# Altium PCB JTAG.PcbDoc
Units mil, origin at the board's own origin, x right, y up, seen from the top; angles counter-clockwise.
Board outline 6010.03 x 2260.03 mil, 2 copper layers (Top, Bottom), stack 62 mil thick; 63 components, 99 nets, 391 pads, 117 vias.
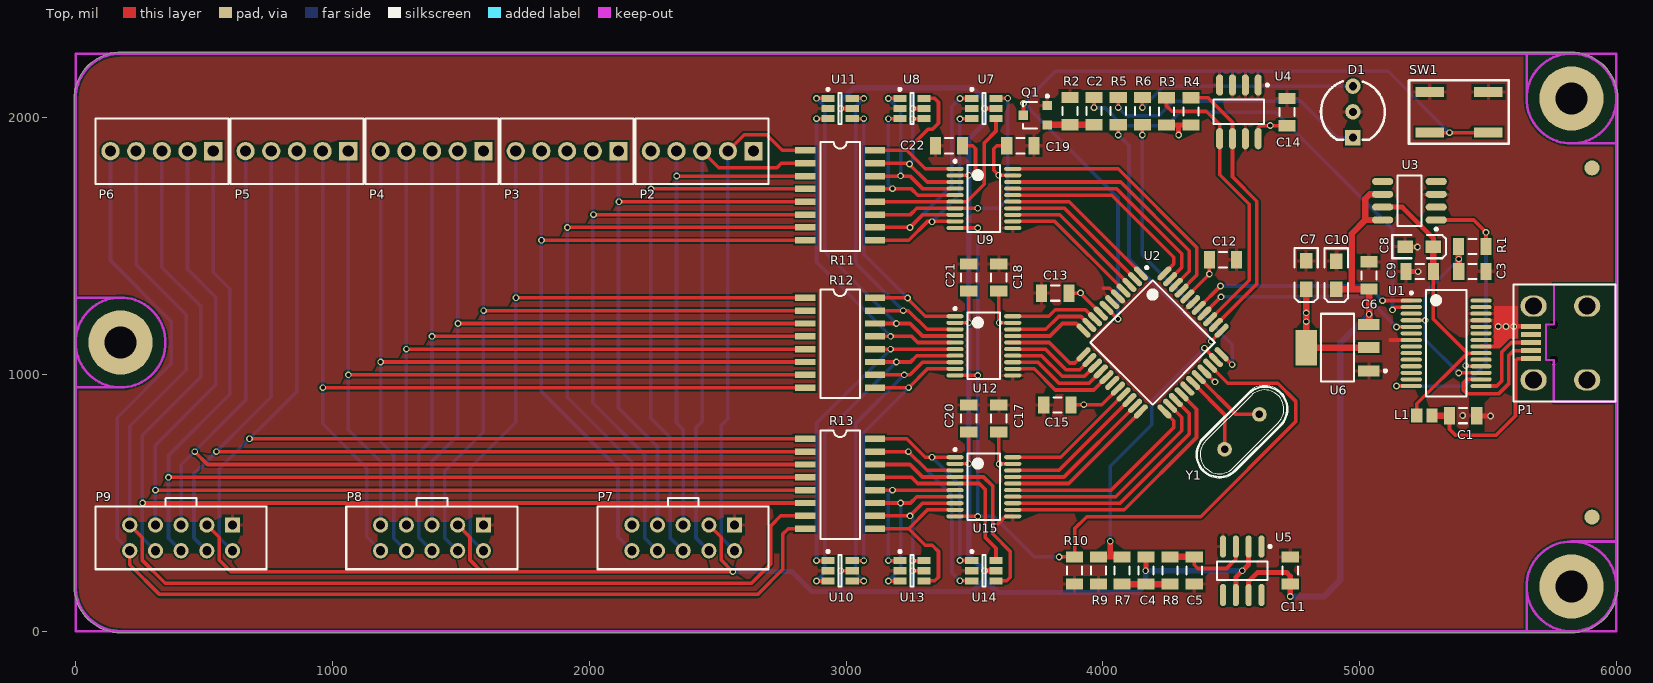
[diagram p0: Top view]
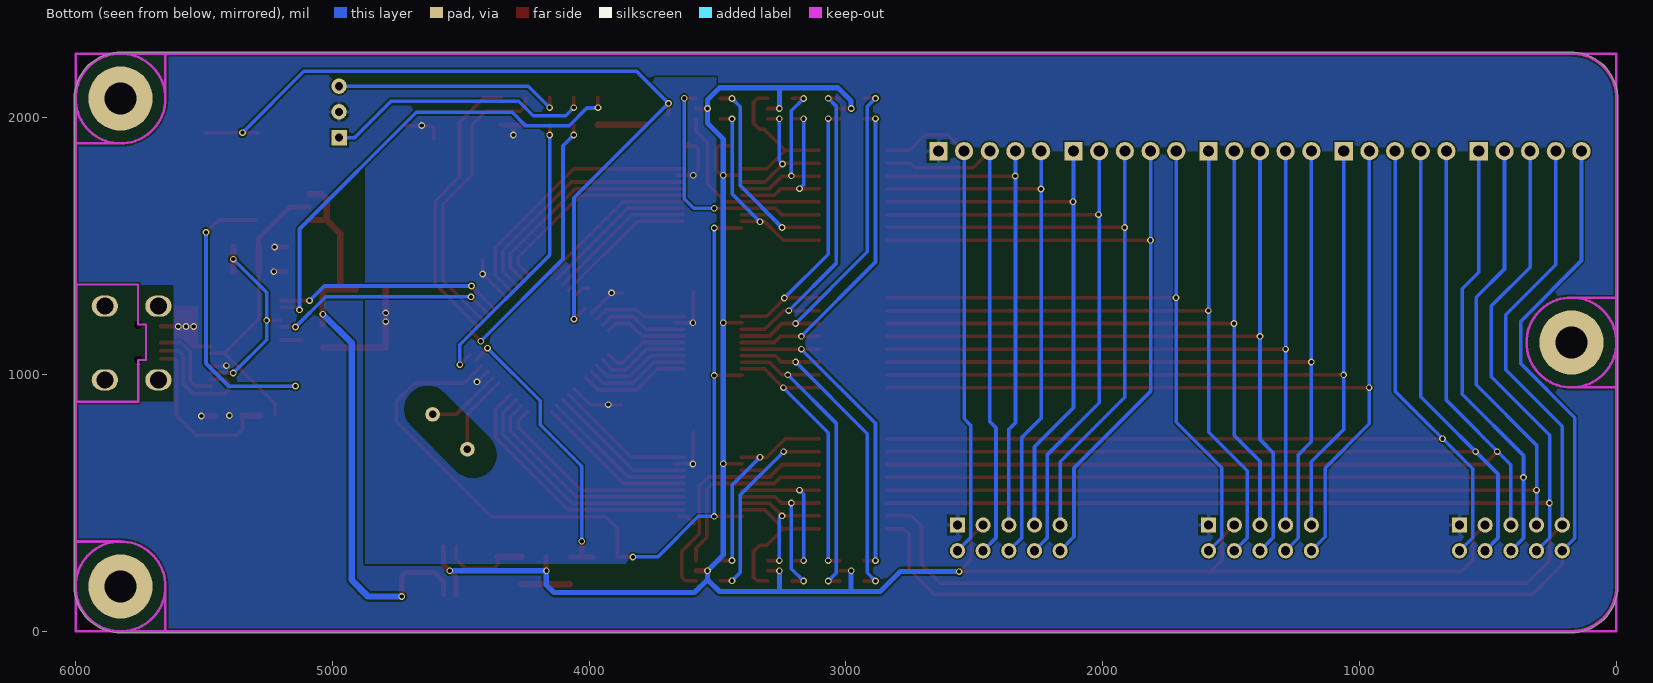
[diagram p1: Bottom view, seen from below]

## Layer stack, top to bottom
Top Solder: solder mask 0.4, Solder Resist, Dk 3.5
Top: signal copper 1.4
Dielectric1: core 59.2, FR-4, Dk 4.8
Bottom: signal copper 1.4
Bottom Solder: solder mask 0.4, Solder Resist, Dk 3.5

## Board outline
-5.02,176 -5.01,2084 -4.69,2085.77 cw(c175,2075) 164.23,2254.69 166,2255.02 5825,2255.02 cw(c5825,2075) 6005.02,2075 6005.01,2074.97 6005.02,175 cw(c5825,175) 5825,-5.01 175,-5.02 174.93,-5.01 cw(c175,175)

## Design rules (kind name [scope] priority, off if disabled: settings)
Clearance Clearance_P1 [InComponent('P1')] p1: gap=0 ignorepadtopadclearanceinfootprint=FALSE
Clearance [All] p2: gap=7 ignorepadtopadclearanceinfootprint=FALSE
ComponentClearance [All] p1 off: gap=0 collisioncheckmode=3 verticalgap=10 showdistances=FALSE
FabricationTestPointUsage TestPointUsage [All] p1: valid=0 allowmultiple=FALSE
FabricationTestpoint Testpoint [All] p1: side=3 testpointundercomponent=TRUE minsize=40 maxsize=100 preferedsize=60 minholesize=0 maxholesize=40 preferedholesize=32 testpointgrid=1 allowsidetop=TRUE allowsidebottom=TRUE usegrid=TRUE gridtolerance=0.01
HoleSize [All] p1: absolutevalues=TRUE maxlimit=250 minlimit=10 maxpercent=80.000 minpercent=20.000
MinimumAnnularRing MinimumAnnularRing_1 [(IsVia)] p1: minimumring=5
MinimumAnnularRing [All] p2: minimumring=7
PolygonConnect [IsVia] p1: connectstyle=Direct reliefconductorwidth=10 reliefentries=4 polygonreliefangle="90 Angle" airgapwidth=10
PolygonConnect PolygonConnect_1 [All] p2: connectstyle=Relief reliefconductorwidth=14 reliefentries=4 polygonreliefangle="90 Angle" airgapwidth=10
RoutingVias [All] p1: holewidth=16 width=26 viastyle="Through Hole" minholewidth=10 minwidth=20 maxholewidth=16 maxwidth=26
SilkToSolderMaskClearance SilkscreenOverComponentPads [IsPad] p1: minsilkscreentomaskgap=10 clearancetoexposedcopper=TRUE
SolderMaskExpansion SolderMaskExpansion_1 [(IsVia)] p1: expansion=-15 istentingtop=FALSE
SolderMaskExpansion [All] p2: expansion=4 istentingtop=FALSE
UnRoutedNet [InNamedPolygon('FILL')] p1:
Width [All] p1: maxlimit=40 minlimit=7 preferedwidth=7
24 further rules are at their usual default settings.

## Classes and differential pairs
component class JTAG-Target: C17 C18 C19 C20 C21 C22 P2 P3 P4 P5 P6 P7 P8 P9 R10 R11 R12 R13 U7 U8 U9 U10 U11 U12 U13 U14 U15
component class JTAG-Main: C1 C2 C3 C4 C5 C6 C7 C8 C9 C10 C11 C12 C13 C14 C15 D1 L1 P1 Q1 R1 R2 R3 R4 R5 R6 R7 R8 R9 SW1 U1 U2 U3 U4 U5 U6 Y1

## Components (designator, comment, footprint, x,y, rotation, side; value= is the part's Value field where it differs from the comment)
C1 "Cap" C1206 5403,840 r180 top
C2 "Cap" C1206 3966,2026 r90 top
C3 "Cap" C1206 5439,1401 r180 top
C4 "Cap" C1206 4168,237 r90 top
C5 "Cap" C1206 4356,237 r90 top
C6 "Cap" C1206 5037,1386 r270 top
C7 "Cap Pol1" "TC3216 (A)" 4792,1388 r180 top
C8 "Cap Pol1" "TC3216 (A)" 5232,1498 r270 top
C9 "Cap" C1206 5234,1401 r0 top
C10 "Cap Pol1" "TC3216 (A)" 4909,1387 r180 top
C11 "Cap" C1206 4730,237 r270 top
C12 "Cap" C1206 4468,1447 r180 top
C13 "Cap" C1206 3815,1317 r0 top
C14 "Cap" C1206 4717,2022 r270 top
C15 "Cap" C1206 3823,882 r0 top (schematic designator C16)
C17 "Cap" C1206 3595,829 r270 top
C18 "Cap" C1206 3595,1378.15 r270 top
C19 "Cap" C1206 3679,1891 r180 top
C20 "Cap" C1206 3478,829 r270 top
C21 "Cap" C1206 3478,1378 r270 top
C22 "Cap" C1206 3401,1891 r0 top
D1 "WP59EGW" WP59EGW 4974,2023 r0 top
L1 "Inductor" C0805 5252,841 r180 top
P1 "UX60-MB-5S8" "HRS UX60-MB-5S8 MINI-USB - NO SLOTS" 5885.92,1266.73 r180 top
P2 "TE 282834-5" TE282834-5 2440,1870 r180 top
P3 "TE 282834-5" TE282834-5 1914,1870 r180 top
P4 "TE 282834-5" TE282834-5 1388,1870 r180 top
P5 "TE 282834-5" TE282834-5 862,1870 r180 top
P6 "TE 282834-5" TE282834-5 336,1870 r180 top
P7 "961210-6404-AR" "HDR2X5 - SHROUD" 2566,414 r180 top
P8 "961210-6404-AR" "HDR2X5 - SHROUD" 1588,414 r180 top
P9 "961210-6404-AR" "HDR2X5 - SHROUD" 611,414 r180 top
Q1 "2N3904" SOT23-3 3737,2010 r90 top
R1 "Res1" C1206 5438.85,1499 r180 top
R2 "Res1" C1206 3872,2026 r270 top
R3 "Res1" C1206 4248,2025 r270 top
R4 "Res1" C1206 4343,2025 r270 top
R5 "Res1" C1206 4060,2026 r270 top
R6 "Res1" C1206 4154,2026 r270 top
R7 "Res1" C1206 4075,237 r90 top
R8 "Res1" C1206 4262,237 r270 top
R9 "Res1" C1206 3983,237 r90 top
R10 "Res1" C1206 3890,237 r90 top
R11 "4816P-1-102LF" "SO-G16 - WIDE" 2841.35,1873 r270 top
R12 "4816P-1-102LF" "SO-G16 - WIDE" 2841,1299 r270 top
R13 "4816P-1-102LF" "SO-G16 - WIDE" 2841.02,750 r270 top
SW1 "SPST" "C&K KSC SPST SWITCH" 5501.35,2100.48 r180 top
U1 "FT232RL" SOP65P780-28BN 5337,1122 r0 top
U2 "PROPELLER (P8X32A-Q44)" TQFP80P1200X1200-44AN 4194,1125 r315 top locked
U3 "MIC2025-2YM" SOIC127P600-8BM 5194,1677 r180 top
U4 "24LC512-I/SN" SOIC127P600-8BM 4530,2023 r270 top
U5 "AD8655ARZ" R-8_N 4543,236 r270 top
U6 "LD1117S33" SOT-223 4914,1105 r90 top
U7 "NUP4302MR6" TSOP-6_M 3537,2036 r0 top
U8 "NUP4302MR6" TSOP-6_M 3257.02,2036 r0 top
U9 "TXS0108EPWR" SOP65P640-20AN 3537,1686 r0 top
U10 "NUP4302MR6" TSOP-6_M 2977,236 r0 top
U11 "NUP4302MR6" TSOP-6_M 2977,2036 r0 top
U12 "TXS0108EPWR" SOP65P640-20AN 3537,1112 r0 top
U13 "NUP4302MR6" TSOP-6_M 3257.02,236 r0 top
U14 "NUP4302MR6" TSOP-6_M 3537,236 r0 top
U15 "TXS0108EPWR" SOP65P640-20AN 3537,563 r0 top
Y1 "5.0MHz" XTL_HC49-4H 4542,777 r45 top

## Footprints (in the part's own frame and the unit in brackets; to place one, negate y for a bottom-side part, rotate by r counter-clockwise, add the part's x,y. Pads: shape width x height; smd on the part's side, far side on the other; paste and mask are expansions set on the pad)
C0805 [mm] "Chip Capacitor, Body 2.0x1.3mm, IPC High Density"
  rect 1.1x1.4 smd: 1(-0.75,0) 2(0.75,0)
  body extent -1.1,-0.73 1.1,0.72, height 1.4
C1206 [mm] "Chip Capacitor, Body 3.2x1.6mm, IPC High Density"
  rect 1.1x1.7 smd: 1(-1.35,0) 2(1.35,0)
  silkscreen extent -0.4,-0.75 0.4,0.75, body extent -1.7,-0.9 1.7,0.9, height 1.3
"C&K KSC SPST SWITCH" [mm] "J-Lead"
  rect 2.8x1 smd: 1(0,4) 1(5.8,4) 2(0,0) 2(5.8,0)
  silkscreen extent -2.03,-1.14 7.85,5.13
"HDR2X5 - SHROUD" [mm]
  rect 1.5x1.5 hole 0.9: 1(0,0)
  round 1.5 hole 0.9: 2(0,2.54) 3(2.54,0) 4(2.54,2.54) 5(5.08,0) 6(5.08,2.54) 7(7.62,0) 8(7.62,2.54) 9(10.16,0) 10(10.16,2.54)
  silkscreen extent -3.38,-2.67 13.56,4.37
"HRS UX60-MB-5S8 MINI-USB - NO SLOTS" [mm]
  oval 2.6x2.1 hole 1.7: 0(0,7.3) 0(0,0) 0(5.3,7.3) 0(5.3,0)
  round 0.9 hole 0.9 unplated: 0(3.3,5.35) 0(3.3,1.85)
  rect 2x0.5 smd: 1(5.55,5.2) 2(5.55,4.4) 3(5.55,3.6) 4(5.55,2.8) 5(5.55,2)
  Keep-Out Layer lines w0.203: 4.089,5.348 3.302,5.348 3.302,9.462 -2.794,9.462 -2.794,-2.145 3.277,-2.145 3.277,1.842 4.089,1.842 4.089,5.348
  silkscreen extent -2.8,-2.15 7.3,9.45
R-8_N [mm] "SOIC, 8-Leads, Body 4.9x3.9mm, Pitch 1.27mm, IPC Medium Density"
  oval 2.2x0.6 smd: 1(-2.4,1.905) 2(-2.4,0.635) 3(-2.4,-0.635) 4(-2.4,-1.905) 5(2.4,-1.905) 6(2.4,-0.635) 7(2.4,0.635) 8(2.4,1.905)
  silkscreen extent -2.52,-2.5 0.9,2.88, body extent -1.95,-2.45 1.95,2.45, height 1.75
"SO-G16 - WIDE" [mil]
  rect 25x79 smd: 1(0,0) 2(50,0) 3(100,0) 4(150,0) 5(200,0) 6(250,0) 7(300,0) 8(350,0) 9(350,271.65) 10(300,271.65) 11(250,271.65) 12(200,271.65) 13(150,271.65) 14(100,271.65) 15(50,271.65) 16(0,271.65)
  silkscreen extent -32,59 391,213
SOIC127P600-8BM [mm] "SOIC, 8-Leads, Body 4.9x3.9mm, Pitch 1.27mm, IPC Low Density"
  oval 2.1x0.7 smd: 1(-2.65,1.905) 2(-2.65,0.635) 3(-2.65,-0.635) 4(-2.65,-1.905) 5(2.65,-1.905) 6(2.65,-0.635) 7(2.65,0.635) 8(2.65,1.905)
  silkscreen extent -2.78,-2.5 1.2,2.93, body extent -2,-2.5 2,2.5, height 2.59
SOP65P640-20AN [mm] "SOP, 20-Leads, Body 6.5x4.4mm, Pitch 0.65mm, IPC Medium Density"
  oval 1.7x0.4 smd: 1(-2.85,2.925) 2(-2.85,2.275) 3(-2.85,1.625) 4(-2.85,0.975) 5(-2.85,0.325) 6(-2.85,-0.325) 7(-2.85,-0.975) 8(-2.85,-1.625) 9(-2.85,-2.275) 10(-2.85,-2.925) 11(2.85,-2.925) 12(2.85,-2.275) 13(2.85,-1.625) 14(2.85,-0.975) 15(2.85,-0.325) 16(2.85,0.325) 17(2.85,0.975) 18(2.85,1.625) 19(2.85,2.275) 20(2.85,2.925)
  silkscreen extent -2.97,-3.3 1.6,3.8, body extent -2.25,-3.3 2.25,3.3, height 1.45
SOP65P780-28BN [mm] "SOP, 28-Leads, Body 10.2x5.3mm, Pitch 0.65mm, IPC Medium Density"
  oval 2.1x0.4 smd: 1(-3.45,4.225) 2(-3.45,3.575) 3(-3.45,2.925) 4(-3.45,2.275) 5(-3.45,1.625) 6(-3.45,0.975) 7(-3.45,0.325) 8(-3.45,-0.325) 9(-3.45,-0.975) 10(-3.45,-1.625) 11(-3.45,-2.275) 12(-3.45,-2.925) 13(-3.45,-3.575) 14(-3.45,-4.225) 15(3.45,-4.225) 16(3.45,-3.575) 17(3.45,-2.925) 18(3.45,-2.275) 19(3.45,-1.625) 20(3.45,-0.975) 21(3.45,-0.325) 22(3.45,0.325) 23(3.45,0.975) 24(3.45,1.625) 25(3.45,2.275) 26(3.45,2.925) 27(3.45,3.575) 28(3.45,4.225)
  silkscreen extent -3.57,-5.25 2,5.25, body extent -2.8,-5.25 2.8,5.25, height 2
SOT23-3 [mm]
  rect 0.9x0.95 smd: 1(0.95,-1.175) 2(-0.95,-1.175) 3(0,1.175)
  silkscreen extent -1.33,-1.32 2.01,1.19
SOT-223 [mm] "SOT-223/SC-73; 4 Leads; Body 6.7 x 7.3 mm, inc. leads (LxW max)"
  rect 1.1x2.15 smd: 1(-2.3,-3.1) 2(0,-3.1) 3(2.3,-3.1)
  rect 3.5x2.15 smd: 4(0,3.1)
  silkscreen extent -3.35,-4.85 3.35,1.62
"TC3216 (A)" [mil]
  rect 50x60 smd: 1(0,55) 2(0,-55)
  silkscreen extent -45,-105 45,105
TE282834-5 [mm] "Terminal Block, Side Entrance, 5 position, 2.54mm P"
  rect 1.8x1.8 hole 1.1: 1(-5.08,0)
  round 1.8 hole 1.1: 2(-2.54,0) 3(0,0) 4(2.54,0) 5(5.08,0)
  silkscreen extent -6.58,-3.25 6.58,3.25
TQFP80P1200X1200-44AN [mm] "Thin QFP, 44-Leads, Body 10x10mm, Pitch 0.8mm, IPC Medium Density"
  oval 1.75x0.55 smd: 1(-5.65,4) 2(-5.65,3.2) 3(-5.65,2.4) 4(-5.65,1.6) 5(-5.65,0.8) 6(-5.65,0) 7(-5.65,-0.8) 8(-5.65,-1.6) 9(-5.65,-2.4) 10(-5.65,-3.2) 11(-5.65,-4) 23(5.65,-4) 24(5.65,-3.2) 25(5.65,-2.4) 26(5.65,-1.6) 27(5.65,-0.8) 28(5.65,0) 29(5.65,0.8) 30(5.65,1.6) 31(5.65,2.4) 32(5.65,3.2) 33(5.65,4)
  oval 0.55x1.75 smd: 12(-4,-5.65) 13(-3.2,-5.65) 14(-2.4,-5.65) 15(-1.6,-5.65) 16(-0.8,-5.65) 17(0,-5.65) 18(0.8,-5.65) 19(1.6,-5.65) 20(2.4,-5.65) 21(3.2,-5.65) 22(4,-5.65) 34(4,5.65) 35(3.2,5.65) 36(2.4,5.65) 37(1.6,5.65) 38(0.8,5.65) 39(0,5.65) 40(-0.8,5.65) 41(-1.6,5.65) 42(-2.4,5.65) 43(-3.2,5.65) 44(-4,5.65)
  silkscreen extent -5.77,-4.35 4.35,4.95, body extent -5,-5 5,5, height 1.2
TSOP-6_M [mm] "SOT23, 6-Leads, Body 3x1.5mm, Pitch 1mm, Lead Span 2.7mm, IPC Low Density"
  rect 1.3x0.7 smd: 1(-1.2,1) 2(-1.2,0) 3(-1.2,-1) 4(1.2,-1) 5(1.2,0) 6(1.2,1)
  silkscreen extent -1.32,-1.55 0.15,2.02, body extent -0.9,-1.55 0.9,1.55, height 1.1
WP59EGW [mil] "T-1 3/4 (mm) Bi-Color Indicator Lamp"
  rect 60x60 hole 32: 1(0,-100)
  round 60 hole 32: 2(0,0) 3(0,100)
  silkscreen extent -124,-108 124,119
XTL_HC49-4H [mm]
  round 1.45 / inner round 1.35 / far side round 1.45 hole 0.75: 1(-2.44,0) 2(2.44,0)
  silkscreen extent -5.5,-2.32 5.5,2.33

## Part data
C1 C2 C3 C4 C5 C6 C9 C11 C12 C13 C14 C15 C17 C18 C19 C20 C21 C22: "Capacitor"
C7 C8 C10: "Polarized Capacitor (Radial)"
D1: library part SSL-LX5097
L1: "MPZ2012S221A"
P1 P2 P3 P4 P5 P6: library part "Header 5", "Header, 5-Pin"
P7 P8 P9: library part "Header 5X2", "Header, 5-Pin, Dual row"
Q1: "NPN General Purpose Amplifier"
R1 R2 R3 R4 R5 R6 R7 R8 R9 R10: "Resistor"
R11 R12 R13: library part "Res Pack3", "Isolated Resistor Network"
SW1: library part SW-PB, "Switch"
U1: "USB UART Asynchronous Serial Data Transfer Chip"
U2: library part "PROPELLER (ALT)"
U3: library part MIC2025-2, "Single-Channel Power Distribution Switch"
U4: library part M24C02WDW6, "2Kbit Serial I²C Bus EEPROM"
U5: library part AD548AR, "Low-Noise, Precision CMOS Op Amp"
U6: library part LD1117, "LD1117xx 800mA LDO Linear Regulator"
U7 U8 U10 U11 U13 U14: "IC Schottky Diode Array TSOP-6"
Y1: library part XTAL, "Crystal Oscillator"

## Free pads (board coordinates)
  round 250 hole 125: 0(175,1125) 0(5825,175) 0(5825,2075)
  round 59.06 smd paste-31.5 mask+29.53: 1(5905,445) 1(5905,1805)

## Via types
v1: diameter 26, hole 16, Top to Bottom, 117 vias

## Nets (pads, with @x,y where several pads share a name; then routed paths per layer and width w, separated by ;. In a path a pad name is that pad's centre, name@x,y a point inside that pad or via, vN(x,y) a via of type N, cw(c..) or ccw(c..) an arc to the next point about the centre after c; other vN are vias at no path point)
3V3: C7.1 C12.2 C13.2 C14.2 C15.2 C17.2 C18.2 C19.2 R3.2 R4.2 U2.8 U2.18 U2.30 U2.40 U4.8 U6.2 U6.4 U9.19 U12.19 U15.19 | length 1965.1
  Top w14: v1@3595,662.15 C17.2@3595,776 ; v1@3595,1211 C18.2@3595,1324.85 ; v1@3603.43,652.57 U15.19@3667.89,652.57 ; v1@3603.43,1201.57 U12.19@3667.89,1201.57 ; C19.2@3615.85,1885.85 C19.2@3615.85,1899 ; C19.2 3587,1891 3575.85,1879.85 3575.85,1795.15 3595.28,1775.72 U9.19@3659.74,1775.72 ; C13.2@3870.15,1317 3912.92,1317 U2.8 ; C15.2 3995.54,882 U2.18 ; U2.40 4414.85,1390.39 C12.2 ; U2.30 v1@4436.34,971.75 ; U4.8 4605,1962 4611.85,1968.85 C14.2
  Top w20: R3.2 R4.2 ; v1@4295.16,1931.84 4295.16,1971.51
  Top w25: U6.4 U6.2 ; U6.4 C7.1
  other v1: 3596.16,651.84 3926,883.17 4436.88,971.75 3596.16,1201.84 4792,1206.17 4792,1240.17 3912.92,1318.17 4414.85,1391.56 3595,1776 4295.16,1933.01 4652,1970.02
5V0: C6.2 C10.1 C11.2 U3.6 U3.8 U5.7 U6.3 | length 2397.5
  Top w20: U5.7 4568,195 4603,230 4715,230 4730,215 C11.2 v1(4730,136)
  Top w25: C10.1@4909,1333 C6.2@5036.85,1333 ; 4969,1334 4969,1549 5022,1602 ; U6.3@5037,1196.5 v1(5037,1234.85) C6.2 ; U3.8 5022,1602 ; U3.6 5039,1702 5022,1685 5022,1602
  Bottom w25: v1(4730,136) 4861,136 4925,200 4925,1122.85 v1(5037,1234.85)
#RES: Q1.3 SW1.1 U2.7 | length 3114
  Top w14: Q1.3@3691,2010.26 v1(3691,2056) ; U2.7@4017.95,1256.51 v1@4059.23,1215.23 ; SW1.1@5288.65,1942 v1(5350,1942) SW1.1@5496.35,1942
  Bottom w14: v1(4059,1216) 4059,1688 v1(3691,2056) 3816,2181 5111,2181 v1(5350,1942)
CH0: P2.2 P7.2 R11.1 | length 1940.6
  Top w14: P2.2 2604,1934 2691,1934 2752,1873 R11.1
  Bottom w14: P2.2 2540,828 2515,803 2515,365 P7.2
CH1: P2.3 P7.4 R11.2 | length 2021.5
  Top w14: P2.3 2504,1806 2731,1806 2748,1823 R11.2
  Bottom w14: P2.3 2440,817 2416,793 2416,364 P7.4
CH2: P2.4 P7.5 R11.3 | length 1967.1
  Top w14: v1(2341,1773) R11.3
  Bottom w14: P2.4 2340,812 2366,786 P7.5
CH3: P2.5 P7.6 R11.4 | length 2208.5
  Top w14: v1(2241,1723) R11.4
  Bottom w14: P2.5 2240,831 2315,756 2315,365 P7.6
CH4: P3.1 P7.7 R11.5 | length 2244.3
  Top w14: v1(2116,1673) R11.5
  Bottom w14: P3.1 2114,871 2266,719 P7.7
CH5: P3.2 P7.8 R11.6 | length 2484.7
  Top w14: v1(2017,1623) R11.6
  Bottom w14: P3.2 2014,890 2217,687 2217,363 P7.8
CH6: P3.3 P7.9 R11.7 | length 2486.7
  Top w14: v1(1915,1573) R11.7
  Bottom w14: P3.3 1914,912 2166,660 P7.9
CH7: P3.4 P7.10 R11.8 | length 2729.1
  Top w14: v1(1814,1523) R11.8
  Bottom w14: P3.4 1814,934 2112,636 2112,368 P7.10
CH8: P3.5 P8.2 R12.1 | length 2776.4
  Top w14: v1(1715,1299) R12.1
  Bottom w14: P8.2 1537,365 1537,637 1714,814 P3.5
CH9: P4.1 P8.4 R12.2 | length 2890.8
  Top w14: v1(1589,1249) R12.2
  Bottom w14: P8.4 1438,364 1438,626 1588,776 P4.1
CH10: P4.2 P8.5 R12.3 | length 2849.4
  Top w14: v1(1489,1199) R12.3
  Bottom w14: P8.5 1388,663 1488,763 P4.2
CH11: P4.3 P8.6 R12.4 | length 3051.2
  Top w14: v1(1388,1149) R12.4
  Bottom w14: P8.6 1337,365 1337,696 1388,747 P4.3
CH12: P4.4 P8.7 R12.5 | length 3009
  Top w14: v1(1288,1099) R12.5
  Bottom w14: P8.7 P4.4
CH13: P4.5 P8.8 R12.6 | length 3248.4
  Top w14: v1@1190,1049 R12.6
  Bottom w14: P4.5 1188,738 1239,687 1239,363 P8.8
  other v1: 1188,1049
CH14: P5.1 P8.9 R12.7 | length 3287.2
  Top w14: v1(1062,999) R12.7
  Bottom w14: P5.1 1062,786 1188,660 P8.9
CH15: P5.2 P8.10 R12.8 | length 3527.6
  Top w14: v1(963,949) R12.8
  Bottom w14: P5.2 962,808 1134,636 1134,368 P8.10
CH16: P5.3 P9.2 R13.1 | length 3866.2
  Top w14: v1(677,750) R13.1
  Bottom w14: P9.2 560,365 560,633 862,935 P5.3
CH17: P5.4 P9.4 R13.2 | length 3994.4
  Top w14: v1(548,700) R13.2
  Bottom w14: P9.4 461,364 461,613 762,914 P5.4
CH18: P5.5 P9.5 R13.3 | length 3958.4
  Top w14: v1(464,700) 514,650 R13.3 ; v1@467,704 v1@467.5,703.5
  Bottom w14: P9.5 411,649 662,900 P5.5
CH19: P6.1 P9.6 R13.4 | length 4180.4
  Top w14: v1(362,600) R13.4
  Bottom w14: P9.6 362,363 362,685 600,923 600,1334 536,1398 P6.1
CH20: P6.2 P9.7 R13.5 | length 4128.9
  Top w14: v1(311,550) R13.5
  Bottom w14: P9.7 311,725 546,960 546,1301 436,1411 P6.2
CH21: P6.3 P9.8 R13.6 | length 4317.7
  Top w14: v1(261,500) R13.6@2845,500
  Bottom w14: P9.8 260,365 260,764 487,991 487,1267 336,1418 P6.3
CH22: P6.4 P9.9 R13.7 | length 4598.3
  Top w14: P9.9 259,366 259,278 349,188 2632,188 2706,262 2706,410 2746,450 R13.7
  Bottom w14: P9.9 211,799 431,1019 431,1233 236,1428 P6.4
CH23: P6.5 P9.10 R13.8 | length 4682.2
  Top w14: P9.10 211,260 327,144 2656,144 2754,242 2754,379 2775,400 R13.8 R13.8@2843,400
  Bottom w14: P6.5 136,1443.95 372.95,1206.99 372.95,1043.01 162,832.05 162,363 P9.10
DACOUT: R7.2 R9.2 U2.32 | length 1120.9
  Top w14: v1(4396,1103) U2.32
  Top w20: R9.2 4029,290.15 ; v1(4029,351) 4029,290.15 ; R7.2 4029,290.15
  Bottom w14: v1(4029,351) 4029,643 4191,805 4191,898 v1(4396,1103)
GND: C1.1 C3.1 C5.1 C6.1 C7.2 C8.2 C9.1 C10.2 C11.1 C12.1 C13.1 C14.1 C15.1 C17.1 C18.1 C19.1 C20.1 C21.1 C22.1 D1.2 P1.5 P2.1 P7.1 P8.1 P9.1 Q1.1 R2.1 R9.1 R10.1 SW1.2 U1.7 U1.18 U1.21 U1.25 U1.26 U2.5 U2.6 U2.17 U2.27 U2.39 U3.3 U4.1 U4.2 U4.3 U4.4 U4.7 U5.4 U6.1 U7.2 U8.2 U9.11 U10.2 U11.2 U12.11 U13.2 U14.2 U15.11 | length 656.1
  Top w14: 3592,419 3620.84,447.84 U15.11 ; 4002,1336 4027.54,1336 U2.5 ; 5119.2,1134.8 U1.7 ; v1(5413,1035) 5415.57,1032.43 U1.18 ; U1.21 5524.2,1109.2 ; v1@5574,1187 v1@5574.99,1187.99
  Top w18: v1@5574.99,1187.99 P1.5
  Top w20: C8.2@5178,1497 v1(5225,1497) ; C9.1 v1(5227.85,1401) ; C1.1@5457.15,839 v1(5510,839) ; 5541,1124 5565,1148 ; 5543,1112 5577,1146
  other v1: 5401,841 5540,1187 5570,1187 5600,1187
LEDG: R6.2 U2.33 | length 1137.1
  Top w14: v1(4154,1933.01) R6.2 ; U2.33 v1@4503.15,1038.56 ; v1@4503.42,1038.29 v1@4503.92,1037.79
  Bottom w14: v1(4154,1933.01) 4154,1466 4503.69,1116.31 v1(4503.69,1038.56)
LEDR: R5.2 U2.34 | length 1050.6
  Top w14: v1(4060,1933.01) R5.2 ; v1@4421.87,1130.16 U2.34
  Bottom w14: v1(4060,1933.01) 4102,1891.01 4102,1450.03 v1(4422.14,1129.89)
NetC1_2: C1.2 L1.1 P1.1 | length 698.4
  Top w14: C1.2 5349.85,787.15 5374,763 5530,763 5607,840 5607,1054 5615.01,1062.01 P1.1
  Top w25: L1.1 5282.53,840 C1.2
NetC2_1: C2.1 Q1.2 R2.2 | length 184
  Top w25: Q1.2@3782,1972.85 C2.1
NetC2_2: C2.2 U1.2 | length 1833.9
  Top w14: v1@3966,2038 C2.2 ; v1(5128,1252) 5138.75,1262.75 U1.2
  Bottom w14: v1@3966,2038 4009,2038 4078,1969 4248,1969 4300,2021 4674,2021 5128,1567 v1(5128,1252)
  other v1: 3966,2039.31
NetC3_2: C3.2 R1.2 U1.4 U1.17 | length 779.8
  Top w14: U1.4 v1@5256,1211.57 ; v1@5397.17,1006.84 U1.17@5473,1006.84
  Top w25: C3.2 R1.2@5385.85,1498.85
  Bottom w14: v1(5385.85,1005.85) 5256,1135.7 5256,1319.77 v1(5385.85,1449.62)
  other v1: 5256,1211
NetC4_1: C4.1 R7.1 R8.2 | length 187
  Top w25: R7.1 C4.1 R8.2
NetC5_2: C5.2 R8.1 U5.3 | length 357.3
  Top w14: C5.2 4356,259 4370,245 4482,245 4518,281 U5.3
  Top w25: R8.1 C5.2
NetD1_1: D1.1 R5.1 | length 1048.4
  Top w14: v1(4060,2039.31) R5.1
  Bottom w14: v1(4060,2039.31) 4091.31,2008 4218,2008 4274,2064 4772,2064 4913,1923 D1.1
NetD1_3: D1.3 R6.1 | length 894.5
  Top w14: v1(4154,2039.31) R6.1
  Bottom w14: v1(4154,2039.31) 4237.69,2123 D1.3
NetR1_1: R1.1 U1.14 U3.1 | length 1222
  Top w14: v1@5143.51,955.66 U1.14 ; U3.1 5444,1602 v1(5492,1554) R1.1
  Bottom w14: v1(5143.51,955.28) 5404.28,955.28 5492,1043 v1(5492,1554)
NetR10_2: R10.2 U2.31 U9.10 U12.10 U15.10 | length 3471.8
  Top w14: U15.10@3405.11,447.84 v1@3501,447.84 ; U12.10@3405.11,996.84 v1@3513,996.84 ; U9.10@3408.11,1570.84 v1@3513,1570.84 ; v1@3830,290.15 R10.2 3890,400 3937,447 4381,447 4752,818 4752,895 4681,966 4486.63,966 U2.31
  Bottom w14: v1(3513,997) v1(3513,448) 3575,448 3733,290 ; v1@3513,1009 v1@3513,1568 ; 3734,290 v1(3830,290)
  other v1: 3513,1571
NetR11_9: R11.9 U7.3 U9.9 | length 825.9
  Top w14: R11.9@3103.46,1523 3244,1523 3317.43,1596.43 3405.11,1596.43 U9.9@3408.11,1596.43 ; v1(3444.16,1995.84) U7.3@3488.97,1995.84
  Bottom w14: v1(3335,1595) 3443,1703 3443,1994.68 v1(3444.16,1995.84)
NetR11_10: R11.10 U7.1 U9.8 | length 952.5
  Top w14: R11.10@3103.46,1573 v1(3249,1573) 3298.02,1622.02 3405.11,1622.02 U9.8@3408.11,1622.02 ; v1(3444,2075) U7.1@3488.81,2075
  Bottom w14: v1(3249,1573) 3412,1736 3412,2043 v1(3444,2075)
NetR11_11: R11.11 U7.6 U9.7 | length 987.9
  Top w14: R11.11@3103.46,1623 3251,1623 3275.61,1647.61 U9.7@3405.11,1647.61 ; U9.7@3405.27,1647.77 v1(3513,1647.77) ; U7.6@3585.03,2076.16 v1(3629.84,2076.16)
  Bottom w14: v1(3513,1647.77) 3592.77,1647.77 3629.84,1684.84 v1(3629.84,2076.16)
NetR11_12: R11.12 U7.4 U9.6 | length 737.2
  Top w14: R11.12@3103.66,1673.2 3405.11,1673.2 3470.2,1673.2 3538,1741 3538,1902 3584.24,1948.24 U7.4
NetR11_13: R11.13 U8.3 U9.5 | length 635.3
  Top w14: R11.13@3103.46,1723 R11.13 3255,1723 3279.2,1698.8 U9.5@3405.11,1698.8 ; v1(3165.12,1996.21) U8.3@3209.93,1996.21
  Bottom w14: v1(3165.12,1996.21) 3165.12,1739.98 v1(3181.1,1724)
NetR11_14: R11.14 U8.1 U9.4 | length 690.8
  Top w14: R11.14@3103.46,1773 3249,1773 3297.61,1724.39 U9.4@3408.11,1724.39 ; v1(3164.96,2075.37) U8.1
  Bottom w14: v1(3164.96,2075.37) 3212.95,2027.39 v1(3212.95,1774)
NetR11_15: R11.15 U8.4 U9.3 | length 561.3
  Top w14: R11.15@3103.46,1823 R11.15 3243,1823 3316.02,1749.98 U9.3@3408.11,1749.98 ; v1(3259.61,1996.21) 3304.42,1996.21 U8.4@3304.26,1996.21
  Bottom w14: v1(3247,1820) 3259.61,1832.61 v1(3259.61,1996.21)
NetR11_16: R11.16 U8.6 U9.1 | length 645
  Top w14: R11.16@3103.46,1873 3237,1873 ; U8.6 3345.65,2075.37 3360.02,2061 3360.02,1979 3336.52,1955.5 3319.5,1955.5 3237,1873 ; U9.1@3408.11,1801.16 3308.84,1801.16 3237,1873
NetR12_9: R12.9 U10.6 U12.9 | length 1126
  Top w14: U10.6 v1(3069.05,275.37) ; R12.9@3103.46,949 v1(3244,949) 3317.43,1022.43 U12.9@3408.11,1022.43
  Bottom w14: v1(3069.05,275.37) 3069.05,774.05 v1(3244,949)
NetR12_10: R12.10 U10.4 U12.8 | length 1264.4
  Top w14: U10.4@3024.4,196.21 v1(3069.21,196.21) ; R12.10@3103.46,999 v1(3227,999) 3249,999 3298.02,1048.02 U12.8@3408.11,1048.02
  Bottom w14: v1(3069.21,196.21) 3037.21,228.21 3037.21,809.21 v1(3227,999)
NetR12_11: R12.11 U10.3 U12.7 | length 1341.4
  Top w14: v1(2884.79,196.21) U10.3@2929.6,196.21 ; R12.11@3103.46,1049 3251,1049 3275.61,1073.61 U12.7@3408.11,1073.61
  Bottom w14: v1(2884.79,196.21) 2916.79,228.21 2916.79,769.79 v1(3196,1049)
NetR12_12: R12.12 U10.1 U12.6 | length 1292.6
  Top w14: v1(2884.95,275.37) U10.1 ; R12.12@3103.66,1099.2 U12.6@3408.11,1099.2
  Bottom w14: v1(2884.95,275.37) 2884.95,809.95 v1(3174,1099)
NetR12_13: R12.13 U11.3 U12.5 | length 1326.9
  Top w14: v1(2884.94,1996.63) U11.3 ; R12.13@3103.46,1149 3255,1149 3279.2,1124.8 U12.5@3408.11,1124.8
  Bottom w14: v1(2884.94,1996.63) 2884.94,1438.06 v1(3174,1149)
NetR12_14: R12.14 U11.1 U12.4 | length 1375.3
  Top w14: v1(2884.79,2075.79) U11.1@2929.6,2075.79 ; R12.14@3103.46,1199 3249,1199 3297.61,1150.39 U12.4@3408.11,1150.39
  Bottom w14: v1(2884.79,2075.79) 2916.79,2043.79 2916.79,1478.21 v1(3196,1199)
NetR12_15: R12.15 U11.6 U12.3 | length 1296.7
  Top w14: U11.6@3024.4,2075.79 v1(3069.21,2075.79) ; R12.15@3103.46,1249 3243,1249 3316.02,1175.98 U12.3@3408.11,1175.98
  Bottom w14: v1(3069.21,2075.79) 3037.21,2043.79 3037.21,1434.79 v1(3223,1249)
NetR12_16: R12.16 U11.4 U12.1 | length 1148.7
  Top w14: U11.4 v1(3069.05,1996.63) ; R12.16@3103.46,1299 3237,1299 3308.84,1227.16 U12.1@3408.11,1227.16
  Bottom w14: v1(3069.05,1996.63) 3069.05,1468.95 v1(3240,1298)
NetR13_9: R13.9 U13.4 U15.9 | length 649.7
  Top w14: R13.9@3103.46,400 3244,400 ; U13.4 3345.65,196.63 3360.02,211 3360.02,311 3336.02,335 3309,335 3244,400 ; U15.9@3408.11,473.43 3317.43,473.43 3244,400
NetR13_10: R13.10 U13.6 U15.8 | length 548.7
  Top w14: R13.10@3103.46,450 R13.10 v1(3249,450) 3298.02,499.02 U15.8@3408.11,499.02 ; v1(3259.45,275.37) U13.6
  Bottom w14: v1(3249,450) 3259.45,439.55 v1(3259.45,275.37)
NetR13_11: R13.11 U13.3 U15.7 | length 683.3
  Top w14: R13.11@3103.46,500 3251,500 3275.61,524.61 U15.7@3408.11,524.61 ; v1(3164.8,196.21) U13.3@3209.61,196.21
  Bottom w14: v1(3164.8,196.21) 3212.79,244.2 v1(3212.79,500)
NetR13_12: R13.12 U13.1 U15.6 | length 630.6
  Top w14: R13.12@3103.66,550.2 U15.6@3408.11,550.2 ; v1(3164.96,275.37) U13.1
  Bottom w14: v1(3164.96,275.37) 3164.96,534.07 v1(3180.95,550.05)
NetR13_13: R13.13 U14.6 U15.5 | length 753.1
  Top w14: R13.13@3103.46,600 3255,600 3279.2,575.8 3405.11,575.8 3519.2,575.8 3543,552 3543,365 3584.24,323.76 U14.6
NetR13_14: R13.14 U14.4 U15.4 | length 947.6
  Top w14: R13.14@3103.46,650 3249,650 3297.61,601.39 3405.11,601.39 3535.61,601.39 3571,566 3571,380 3640,311 3640,211 3625.63,196.63 U14.4
NetR13_15: R13.15 U14.3 U15.3 | length 966
  Top w14: R13.15@3103.46,700 v1(3243,700) 3316.02,626.98 3405.11,626.98 U15.3@3408.11,626.98 ; v1(3444,197) U14.3@3488.81,197
  Bottom w14: v1(3243,700) 3412,531 3412,229 v1(3444,197)
NetR13_16: R13.16 U14.1 U15.1 | length 825.4
  Top w14: R13.16@3103.46,750 3237,750 3308.84,678.16 U15.1@3404.11,678.16 ; U15.1@3405.11,678.16 U15.1@3408.11,678.16 ; v1(3444.16,276.16) U14.1@3488.97,276.16
  Bottom w14: v1(3335.16,678.16) 3443,570.32 3443,277.32 v1(3444.16,276.16)
NetU2_28: U2.28 Y1.1 | length 309.5
  Top w14: U2.28 4474.07,844.93 Y1.1
NetU2_29: U2.29 Y1.2 | length 296.4
  Top w14: U2.29 4518.62,844.93 Y1.2
P0: U2.41 U9.20 | length 1048.9
  Top w14: U9.20@3634.89,1801.16 4060.11,1801.16 4365.11,1496.16 4365.11,1386.24 U2.41@4306.86,1327.99
P1: U2.42 U9.18 | length 966.8
  Top w14: U9.18@3634.89,1749.98 4069.29,1749.98 4337.11,1482.16 4337.11,1402.78 U2.42@4284.59,1350.26
P2: U2.43 U9.17 | length 893.7
  Top w14: U9.17@3634.89,1724.39 4052.88,1724.39 4307.11,1470.16 4307.11,1417.33 U2.43@4262.32,1372.53
P3: U2.44 U9.16 | length 818.6
  Top w14: U9.16@3634.89,1698.8 4034.47,1698.8 4276.11,1457.16 4276.11,1430.87 U2.44@4240.04,1394.8
P4: U2.1 U9.15 | length 628.6
  Top w14: U9.15@3634.89,1673.2 3869.77,1673.2 U2.1@4148.18,1394.8
P5: U2.2 U9.14 | length 605
  Top w14: U9.14@3634.89,1647.61 3850.82,1647.61 U2.2@4125.91,1372.53
P6: U2.3 U9.13 | length 581.3
  Top w14: U9.13@3634.89,1622.02 3831.87,1622.02 U2.3@4103.63,1350.26
P7: U2.4 U9.12 | length 557.7
  Top w14: U9.12@3634.89,1596.43 3812.92,1596.43 U2.4@4081.36,1327.99
P8: U2.9 U12.20 | length 364.3
  Top w14: U12.20@3631.89,1227.16 3789.16,1227.16 3815,1253 3932.37,1253 U2.9
P9: U2.10 U12.18 | length 350
  Top w14: U12.18@3631.89,1175.98 3777.98,1175.98 3828,1226 3914.83,1226 U2.10
P10: U2.11 U12.17 | length 325.2
  Top w14: U12.17@3631.89,1150.39 3794.39,1150.39 3843,1199 3897.29,1199 U2.11
P11: U2.12 U12.16 | length 340.6
  Top w14: U12.16@3631.89,1124.8 3791.2,1124.8 3871,1045 3891.29,1045 U2.12
P12: U2.13 U12.15 | length 364.6
  Top w14: U12.15@3631.89,1099.2 3776.8,1099.2 3857,1019 3909.83,1019 U2.13
P13: U2.14 U12.14 | length 388.6
  Top w14: U12.14@3631.89,1073.61 3761.39,1073.61 3842,993 3928.37,993 U2.14
P14: U2.15 U12.13 | length 412.6
  Top w14: U12.13@3631.89,1048.02 3747.98,1048.02 3829,967 3946.92,967 U2.15
P15: U2.16 U12.12 | length 437.4
  Top w14: U12.12@3631.89,1022.43 3732.57,1022.43 3815,940 3964.46,940 U2.16
P16: U2.19 U15.20 | length 551.8
  Top w14: U15.20@3630.89,678.16 3836.24,678.16 U2.19
P17: U2.20 U15.18 | length 586.1
  Top w14: U15.18@3630.89,626.98 3829.6,626.98 U2.20
P18: U2.21 U15.17 | length 609.7
  Top w14: U15.17@3630.89,601.39 3848.55,601.39 U2.21
P19: U2.22 U15.16 | length 633.4
  Top w14: U15.16@3630.89,575.8 3867.51,575.8 U2.22
P20: U2.23 U15.15 | length 823.4
  Top w14: U15.15@3630.89,550.2 4032.2,550.2 4276,794 4276,820.29 U2.23
P21: U2.24 U15.14 | length 898.5
  Top w14: U15.14@3630.89,524.61 4050.61,524.61 4307,781 4307,833.83 U2.24
P22: U2.25 U15.13 | length 971.6
  Top w14: U15.13@3630.89,499.02 4067.02,499.02 4337,769 4337,848.37 U2.25
P23: U2.26 U15.12 | length 1043
  Top w14: U15.12@3630.89,473.43 4083.43,473.43 4365,755 4365,864.92 U2.26
PROPRX: U1.1 U2.38 | length 886.4
  Top w14: U2.38 v1(4458.54,1345) ; v1@5089,1288.34 U1.1
  Bottom w14: v1(4458.54,1345) 5032,1345 v1(5089,1288)
PROPSCL: R4.1 U2.35 U4.6 | length 1096.7
  Top w14: R4.1 4409.85,2078.15 4505,1983 U4.6 4505,1770 4600,1675 4600,1352.83 U2.35
PROPSDA: R3.1 U2.36 U4.5 | length 1138
  Top w14: R3.1 4248,2046 4268,2026 4403,2026 4455,1974 U4.5 4455,1778 4570,1663 4570,1367.37 U2.36
PROPTX: U1.5 U2.37 | length 880.6
  Top w14: U2.37@4395.83,1238.29 v1(4460.34,1302.79) ; v1@5143.51,1185.98 U1.5
  Bottom w14: v1(4460.34,1302.79) 5026.31,1302.79 v1(5143.51,1185.59)
USBDM: P1.2 U1.16 | length 505.4
  Top w14: U1.16 5417.25,981.25 5404,968 5404,940 5418,926 5543,926 5580,963 5580,1073 5600.5,1093.5 P1.2
USBDP: P1.3 U1.15 | length 330.9
  Top w14: U1.15 5533.66,955.66 5553,975 5553,1088 5590,1125 P1.3
VADJ: C4.2 C20.2 C21.2 C22.2 P7.3 P8.3 P9.3 U5.2 U5.6 U7.5 U8.5 U9.2 U10.5 U11.5 U12.2 U13.5 U14.5 U15.2 | length 8666.4
  Top w14: P9.3 559,366 559,278 605,232 v1@2559.5,232 ; P8.3 1536,366 1536,278 1581.5,232.5 ; P7.3 2514,366 2514,278 v1(2559.5,232.5) ; v1(2979.43,236) U10.5 ; v1(2979.43,2036) U11.5 ; v1(3259.45,236) U13.5 ; v1(3259.45,2036) U8.5 ; U15.2@3405.11,652.57 v1@3468.57,652.57 ; U12.2@3405.11,1201.57 v1@3468.57,1201.57 ; U9.2@3420.26,1775.72 3484.72,1775.72 3504.15,1795.15 3504.15,1879.85 3493,1891 C22.2 ; v1(3478,653) C20.2 ; v1(3478,1201.72) C21.2 ; v1(3539.43,2036) U7.5
  Top w20: v1(3539.43,236) U14.5 ; v1@4167,238 4168,239 C4.2 ; U5.6 4518,211 4568,261 U5.2
  Bottom w20: v1@2559.5,233.5 2788.5,233.5 2867,155 2980,155 v1@2980,235.43 ; 2978,155 3275,155 3493,155 3539.43,201.43 ; v1@2980,2036.57 2980,2066 3031,2117 3275,2117 3493,2117 3539.43,2070.57 v1(3539.43,2036) 3539.43,1978.43 3478,1917 v1(3478,1776) v1(3478,1201.72) v1(3478,653) 3478,297.43 v1(3539.43,236) 3539.43,201.43 ; 3259.02,155 v1@3259.02,235.57 ; v1@3259.02,2036.43 3259.02,2117 ; 3589.87,151 3539.43,201.43 ; 3591,151 4137,151 4167,181 v1(4167,236) v1(4543,236)
VUSB: C8.1 C9.2 L1.2 U1.20 U3.7 | length 1127.2
  Top w14: L1.2 5222.47,886.09 5420,1083.61 ; C9.2 5287.15,1216.46 5420,1083.61 ; U1.20 5420,1083.61
  Top w20: U3.7 5166,1652 5287.15,1530.85 C8.1@5287.15,1497.85
  Top w25: C9.2 C8.1@5287.15,1497.85
pads on no net: P1.0 P1.4 U1.3 U1.6 U1.8 U1.9 U1.10 U1.11 U1.12 U1.13 U1.19 U1.22 U1.23 U1.24 U1.27 U1.28 U3.2 U3.4 U3.5 U5.1 U5.5 U5.8

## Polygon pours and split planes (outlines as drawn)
GND on Bottom "GND" (solid, remove dead copper, pour order 8): -43,2294 6043,2294 6043,-56 -43,-56
3V3 on Bottom "3V3" (solid, remove dead copper, pour order 7): 3506,2157 3506,263 4872,263 4872,2157
no net on Top "FILL" (solid, pour order 10): 2949,1775 2946.67,1772.48 2946.67,1478 1768.33,1478 1766,1480.52 1766,1767.45
no net on Top "FILL" (solid, pour order 11): 2964,1342 2959.97,1338.25 2959.97,900 923.03,900 919,903.75 919,1330.76
GND on Top "GND" (solid, remove dead copper, pour order 9): -43,2299 6043,2299 6043,-51 -43,-51
no net on Top "FILL" (solid, pour order 12): 2943,830 2937.47,827.19 2937.47,499 141.53,499 136,501.81 136,821.58
no net on Top "FILL" (solid, pour order 18): 100,303.05 2791,303.05 2791,100 100,100

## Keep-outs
Keep-Out Layer:
  circle w10: c175,1125 r175
  circle w10: c5825,175 r175
  circle w10: c5825,2075 r175
  lines w10: 0,176 ccw(c175,176) 175,1 ; 0,1299 174,1299 ; 0,2075 cw(c175,2075) 175,2250 ; 5,950 179,950 ; 5650,0 5650,174 ; 5650,2074 5650,2248 ; 5821,1900 5995,1900 ; 5824,350 5998,350 ; 0,0 6000,0 6000,2250 0,2250 0,0

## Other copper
Top:
  rectangle net GND: 5523,1102 5545,1140.6
  rectangle net GND: 5523,1140.6 5617,1268
  pour cut-out: 5617,895 5756,895 5756,1350.28 5755.72,1350 5617,1350
  pour cut-out: 5238,1145 5238,1113 5245,1113 5291,1159
  pour cut-out: 5382.99,1151.01 5383.99,1151.01 5386,1149
  pour cut-out: 4016,205 4016,269 4159,269 4156,266 4156,205
  pour cut-out: 3818.98,2050.5 3953.5,2050.5 3955,2049 3955,2000 3821,2000 3818,1997
  pour cut-out: 2663,1905 2664.5,1903.5 2721.5,1903.5 2752,1873 2750,1871 2750,1823 2732,1805 2661,1805
  text "COPPER LAYER TOP" at 7042.04,-1467.97 h49.21
Bottom:
  pour cut-out: 4516.78,623.49 cw(c4452.06,688.21) 4387.33,752.94 4564.11,929.71 cw(c4628.83,864.99) 4693.56,800.26
  pour cut-out: 5617,895 5756,895 5756,1350.28 5755.72,1350 5617,1350
  pour cut-out: 2114,1870 2240,1870 2240,1820 2207,1787
  pour cut-out: 1588,1870 1714,1870 1714,1816 1690,1792
  pour cut-out: 1062,1870 1188,1870 1188,1786 1191,1783
  pour cut-out: 536,1870 662,1870 662,1816 665,1813
  text "COPPER LAYER BOTTOM" at 7042.04,-1818.52 h49.21

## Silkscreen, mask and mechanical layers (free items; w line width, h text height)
Top Paste:
  text "PASTE MASK TOP" at 7043.72,-1113.64 h49.21
Bottom Paste:
  text "PASTE MASK BOTTOM" at 7042.02,-2172.4 h49.21
Top Solder:
  text "SOLDER MASK TOP" at 7042.04,-1349.86 h49.21
Bottom Solder:
  text "SOLDER MASK BOTTOM" at 7042.04,-1936.63 h49.21
Silkscreen Top:
  drawing of 4003 lines, arcs and shapes, not listed
  text "CH23" at 156,2050 h40 r90
  text "CH22" at 256,2050 h40 r90
  text "CH21" at 356,2050 h40 r90
  text "CH20" at 456,2050 h40 r90
  text "CH19" at 556,2050 h40 r90
  text "CH18" at 682,2050 h40 r90
  text "CH17" at 782,2050 h40 r90
  text "CH16" at 882,2050 h40 r90
  text "CH15" at 982,2050 h40 r90
  text "CH14" at 1082,2050 h40 r90
  text "CH13" at 1208,2050 h40 r90
  text "CH12" at 1308,2050 h40 r90
  text "CH11" at 1408,2050 h40 r90
  text "CH10" at 1508,2050 h40 r90
  text "CH9" at 1608,2050 h40 r90
  text "CH8" at 1734,2050 h40 r90
  text "CH7" at 1834,2050 h40 r90
  text "CH6" at 1934,2050 h40 r90
  text "CH5" at 2034,2050 h40 r90
  text "CH4" at 2134,2050 h40 r90
  text "CH3" at 2260,2050 h40 r90
  text "CH2" at 2360,2050 h40 r90
  text "CH1" at 2460,2050 h40 r90
  text "CH0" at 2560,2050 h40 r90
  text "GND" at 2660,2050 h40 r90
  text "STATUS" at 4873,1811 h40
  text "RESET" at 5313,1811 h40
  text "CH22" at 229,531 h40 r90
  text "CH20" at 329,531 h40 r90
  text "CH18" at 429,531 h40 r90
  text "VADJ" at 529,531 h40 r90
  text "GND" at 629,531 h40 r90
  text "CH14" at 1206,531 h40 r90
  text "CH12" at 1306,531 h40 r90
  text "CH10" at 1406,531 h40 r90
  text "VADJ" at 1506,531 h40 r90
  text "GND" at 1606,531 h40 r90
  text "CH6" at 2184,531 h40 r90
  text "CH4" at 2284,531 h40 r90
  text "CH2" at 2384,531 h40 r90
  text "VADJ" at 2484,531 h40 r90
  text "GND" at 2584,531 h40 r90
  text "CH1" at 2484,109.75 h40 r90
  text "CH9" at 1506,94.52 h40 r90
  text "CH8" at 1606,92.61 h40 r90
  text "CH7" at 2184,92.61 h40 r90
  text "CH5" at 2284,92.61 h40 r90
  text "CH3" at 2384,92.61 h40 r90
  text "CH0" at 2584,92.61 h40 r90
  text "CH11" at 1406,80.42 h40 r90
  text "CH21" at 329,74.14 h40 r90
  text "CH19" at 429,65.19 h40 r90
  text "CH16" at 629,65.19 h40 r90
  text "CH17" at 529,63.28 h40 r90
  text "CH15" at 1206,63.28 h40 r90
  text "CH13" at 1306,63.28 h40 r90
  text "CH23" at 229,57 h40 r90
  text "SILKSCREEN TOP" at 7043.72,-1231.75 h49.21
Silkscreen Bottom:
  text "SILKSCREEN BOTTOM" at 7046.25,-2057.5 h49.21
Board Shape:
  lines w10: 0,175 ccw(c175,175) 175,0 5825,0 ccw(c5825,175) 6000,175 6000,2075 ccw(c5825,2075) 5825,2250 166,2250 ; 0,176 0,2084 ; 0,2075 cw(c175,2075) 175,2250
Drill Drawing:
  drawing of 1736 lines, arcs and shapes, not listed
  text "FABRICATION / ASSEMBLY NOTES:" at 2,5474 h59.06
  text "(UNLESS OTHERWISE SPECIFIED)" at 2,5374 h59.06
  text "1. MATERIAL: EPOXY GLASS LAMINATE FR-4" at 2,5174 h59.06
  text "FINISHED COPPER WEIGHT SHALL BE 1 OZ ON ALL LAYERS" at 102,5074 h59.06
  text "2. NUMBER OF ELECTRICAL LAYERS: 2" at 2,4874 h59.06
  text "3. TRACE / SPACE MINIMUM: 0.007\" / 0.007\" (ALL LAYERS)" at 2,4674 h59.06
  text "4. THICKNESS: 0.062\" (FINISHED)" at 6,4474 h59.06
  text "5. FINISH: IMMERSION PLATE EXPOSED AREAS AFTER APPLYING SOLDER MASK WITH ELECTROLESS NICKEL IMMERSION GOLD" at 6,4274 h59.06
  text "6. SOLDER MASK: LIQUID PHOTOIMAGEABLE SOLDER MASK PER IPC-SM-840" at 6,4074 h59.06
  text "COLOR PINK, 10/ 50um THK, BOTH SIDES, AFTER PLATING. REGISTRATION TO BE WITHIN +/- 50um" at 106,3974 h59.06
  text "OF THE ASSOCIATED CIRCUIT LAYER." at 106,3874 h59.06
  text "7. SILKSCREEN: TOP SIDE USING WHITE NONCONDUCTIVE INK." at 6,3674 h59.06
  text "8. RoHS: PARTS SHALL BE RoHS COMPLIANT PER EUROPEAN UNION DIRECTIVE 2002/95/EC." at 4,3435 h59.06
  text "9. THE BOARD MUST BE LEAD-FREE ASSEMBLY PROCESS COMPATIBLE AND BE ABLE TO HANDLE A MINIMUM" at 4,3235 h59.06
  text "OF 5 CYCLES AT 260 DEGREES CELSIUS" at 204,3135 h59.06
  text "10. ALL TEST/QA/QC MARKINGS TO BE PLACED ON BACK SIDE OF PCB" at 4,2935 h59.06
  text ".LEGEND" at 6951.12,-621.08 h60
  text "LAYER TITLE" at 7314.63,-888.31 h59.06
  text ".PCB_FILE_NAME_NO_PATH" at -150.14,-919.88 h70
  text "DRILL DRAWING" at 7037.17,-991.97 h49.21
  text "PCB ARTWORK:" at -107.83,-1177.09 h29.53
  text "COMPANY:" at 1573.27,-1198.75 h39.37
  text "GRAND IDEA STUDIO, INC." at -107.83,-1275.52 h39.37
  text "www.GrandIdeaStudio.com" at -109,-1349 h39.37
  text "TITLE:" at 1573.27,-1513.71 h39.37
  text "JTAGulator" at 1768.15,-1633 h49.21
  text "DRAWN:" at 1573.27,-1828.67 h39.37
  text "Joe Grand" at 1768.15,-1948.75 h49.21
  text "DESIGN FILES DISTRIBUTED UNDER A" at -103.83,-2003.39 h34.45
  text "CREATIVE COMMONS ATTRIBUTION-SHAREALIKE" at -103.83,-2082.13 h34.45
  text "ISSUE:" at 1573.27,-2143.63 h39.37
  text "DATE:" at 2045.71,-2143.63 h39.37
  text "C" at 1799,-2157 h49.21
  text "06-18-2025" at 2340,-2159 h49.21
  text "4.0 INTERNATIONAL LICENSE" at -108.09,-2165.28 h34.45

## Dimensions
0,2250 to 6000,2250 on Mechanical
6000,2250 to 6000,0 on Mechanical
